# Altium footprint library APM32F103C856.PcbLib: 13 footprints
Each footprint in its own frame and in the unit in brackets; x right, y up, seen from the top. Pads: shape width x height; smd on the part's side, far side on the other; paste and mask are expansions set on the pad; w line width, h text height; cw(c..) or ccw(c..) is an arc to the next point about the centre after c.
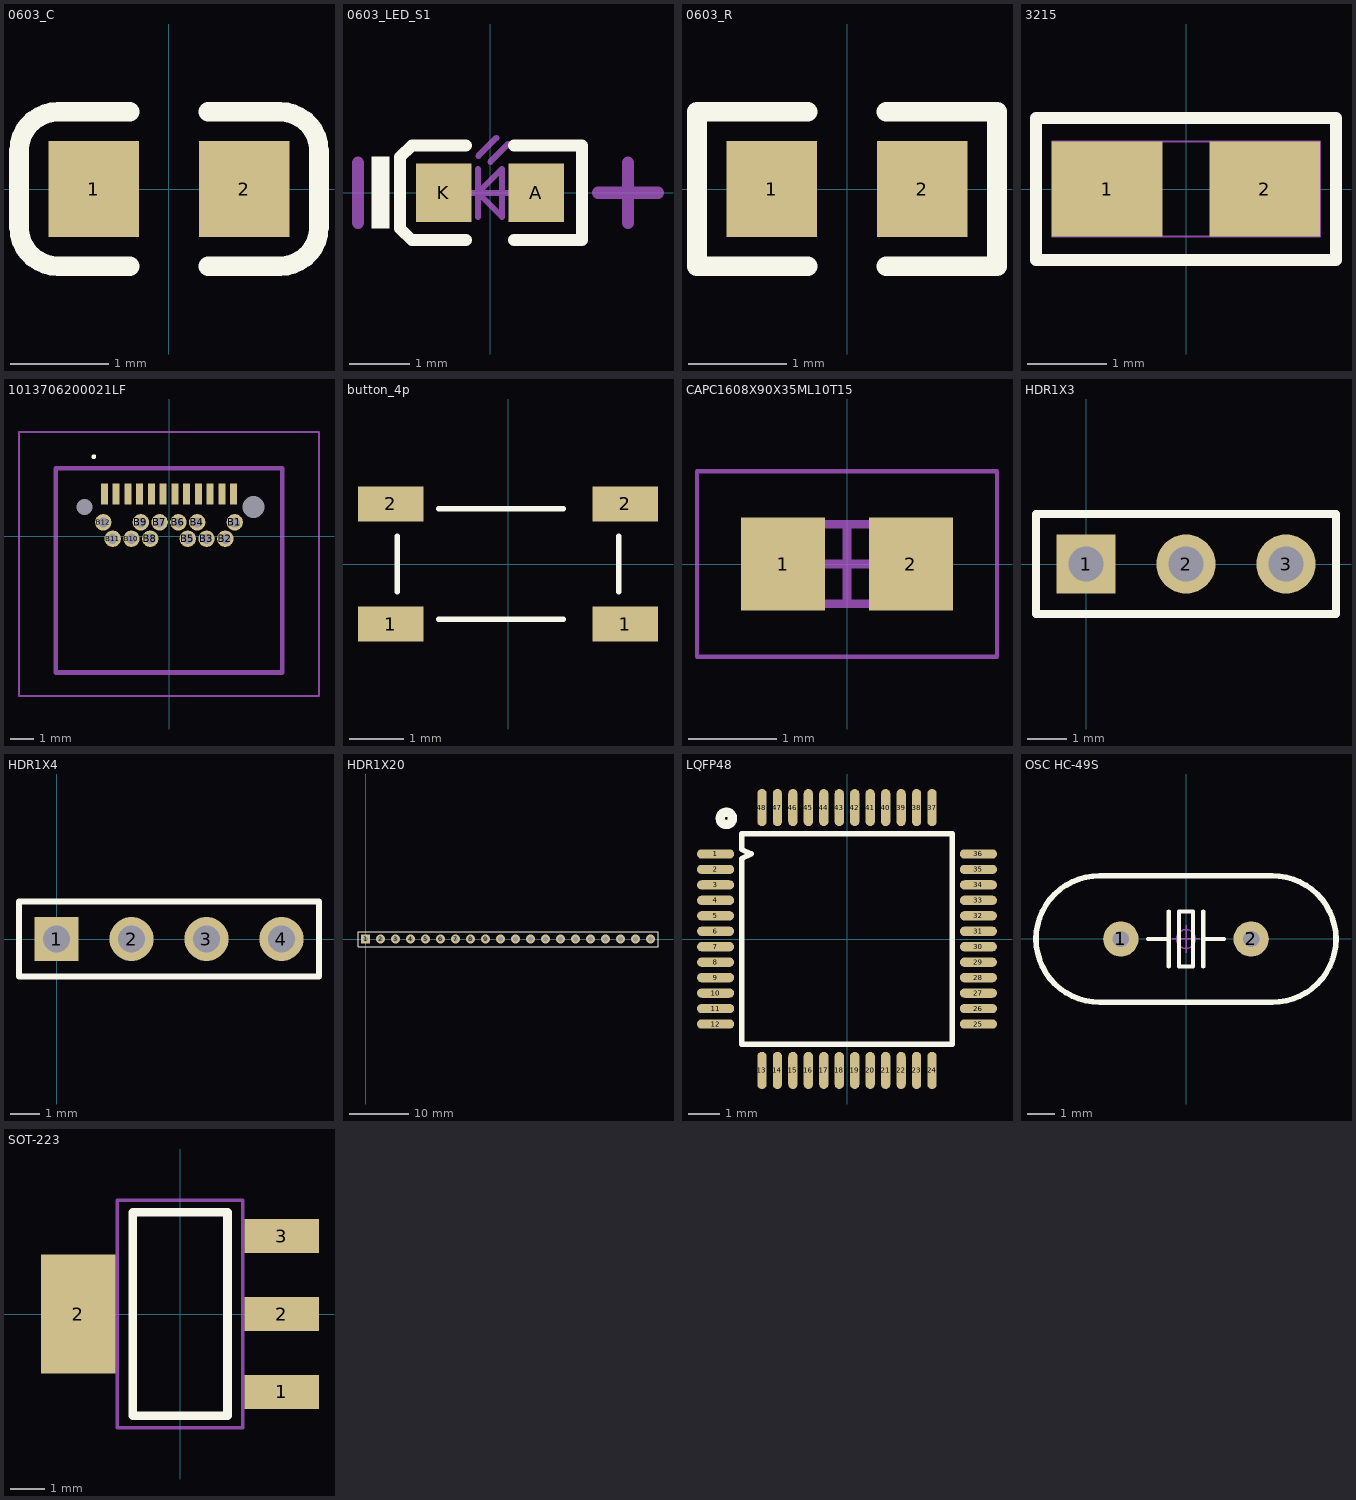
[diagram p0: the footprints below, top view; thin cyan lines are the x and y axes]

## 0603_C [mm]
pads (2):
  rect 0.93x0.98 smd paste+0: 1(-0.77,0)
  rect 0.93x0.98 smd: 2(0.77,0)
Top Overlay:
  lines w0.2: -0.4,-0.79 -1.135,-0.79 cw(c-1.135,-0.39) -1.535,-0.39 -1.535,0.39 cw(c-1.135,0.39) -1.135,0.79 -0.4,0.79 ; 0.4,-0.79 1.135,-0.79 ccw(c1.135,-0.39) 1.535,-0.39 1.535,0.39 ccw(c1.135,0.39) 1.135,0.79 0.4,0.79
3D body "User Library-0603 SMD Capacitor.STEP": height 0.3, standoff 0, extent -0.8,-0.4 0.8,0.4

## 0603_LED_S1 [mm]
pads (2):
  rect 0.93x0.98 smd: A(0.77,0) K(-0.77,0)
Top Overlay:
  rectangle: -1.975,-0.599 -1.675,0.601
  lines w0.2: -0.4,-0.79 -1.3,-0.79 -1.5,-0.597 -1.5,0.597 -1.3,0.79 -0.4,0.79 ; 0.4,-0.79 1.535,-0.79 1.535,0.79 0.4,0.79
Mechanical 13:
  lines w0.1: -0.4,0 0.4,0 ; -0.2,-0.4 -0.2,0.4 ; -0.195,0.617 0.105,0.917 ; 0.005,0.517 0.305,0.817 ; -0.2,0 0.2,-0.4 0.2,0.4 -0.2,0
Mechanical 15:
  lines w0.203: -2.2,-0.5 -2.2,0.5 ; 1.8,0 2.8,0 ; 2.3,-0.5 2.3,0.5
3D body "User Library-LED_0603_R.STEP": height 0.6, standoff 0, extent -0.8,-0.4 0.8,0.4

## 0603_R [mm]
pads (2):
  rect 0.93x0.98 smd: 1(-0.77,0) 2(0.77,0)
Top Overlay:
  lines w0.2: -0.4,-0.79 -1.535,-0.79 -1.535,0.79 -0.4,0.79 ; 0.4,-0.79 1.535,-0.79 1.535,0.79 0.4,0.79
3D body "User Library-RES_1609-0603.STEP": height 0.56, standoff 0, extent -0.85,-0.4 0.85,0.4

## 3215 [mm]
pads (2):
  rect 1.4x1.2 smd: 1(-1,0) 2(1,0)
Top Overlay:
  lines w0.15: -1.9,-0.9 -1.9,0.9 1.9,0.9 1.9,-0.9 -1.9,-0.9
Top Assembly:
  text "Y7" at -0.989,-0.635 h1.27
Mechanical 20:
  lines w0.025: -1.7,-0.6 1.7,-0.6 1.7,0.6 -1.7,0.6 -1.7,-0.6

## 1013706200021LF [mm]
pads (26):
  rect 0.3x0.9 smd: A1(-2.75,1.81) A2(-2.25,1.81) A3(-1.75,1.81) A4(-1.25,1.81) A5(-0.75,1.81) A6(-0.25,1.81) A7(0.25,1.81) A8(0.75,1.81) A9(1.25,1.81) A10(1.75,1.81) A11(2.25,1.81) A12(2.75,1.81)
  round 0.7 hole 0.43: B1(2.8,0.6) B2(2.4,-0.1) B3(1.6,-0.1) B4(1.2,0.6) B5(0.8,-0.1) B6(0.4,0.6) B7(-0.4,0.6) B8(-0.8,-0.1) B9(-1.2,0.6) B10(-1.6,-0.1) B11(-2.4,-0.1) B12(-2.8,0.6)
  round 0.338 hole 0.675 unplated: MH5(-3.6,1.25)
  round 0.475 hole 0.95 unplated: MH6(3.6,1.25)
Top Overlay:
  lines w0.1: -3.2,3.35 cw(c-3.2,3.4) -3.2,3.45 cw(c-3.2,3.4) -3.2,3.35
Mechanical 13:
  lines w0.2: -4.825,-5.8 -4.825,2.9 4.825,2.9 4.825,-5.8 -4.825,-5.8
Mechanical 15:
  lines w0.1: -6.39,-6.8 -6.39,4.45 6.39,4.45 6.39,-6.8 -6.39,-6.8
3D body "10137062-00021LF.stp": height 3.07, standoff -1.13, extent -4.825,-5.76 4.825,2.94

## button_4p [mm]
pads (4):
  rect 1.2x0.65 smd: 1(-2.15,-1.1) 1(2.15,-1.1) 2(-2.15,1.1) 2(2.15,1.1)
Top Overlay:
  lines w0.1: -2.032,-0.508 -2.032,0.508 ; -1.27,-1.016 1.016,-1.016 ; -1.27,1.016 1.016,1.016 ; 2.032,-0.508 2.032,0.508

## CAPC1608X90X35ML10T15 [mm] "Chip Capacitor, 2-Leads, Body 1.7x0.9mm, IPC Low Density"
height 0.9
pads (2):
  rect 0.95x1.05 smd: 1(-0.725,0) 2(0.725,0)
Mechanical 13:
  lines w0.1: -0.85,-0.45 -0.85,0.45 0.85,0.45 0.85,-0.45 -0.85,-0.45
Mechanical 15:
  lines w0.05: -1.7,-1.05 -1.7,1.05 1.7,1.05 1.7,-1.05 -1.7,-1.05
  lines w0.1: -0.45,0 0.45,0 ; 0,-0.45 0,0.45
3D body "CAPC1608X09M.step": height 0.9, standoff 0, extent -0.85,-0.45 0.85,0.45

## HDR1X3 [mm] "Connector; Header; 3 Position"
pads (3):
  rect 1.5x1.5 hole 0.9: 1(0,0)
  round 1.5 hole 0.9: 2(2.54,0) 3(5.08,0)
Top Overlay:
  lines w0.2: -1.27,-1.27 6.35,-1.27 6.35,1.27 -1.27,1.27 -1.27,-1.27

## HDR1X4 [mm] "Connector; Header; 4 Position"
pads (4):
  rect 1.5x1.5 hole 0.9: 1(0,0)
  round 1.5 hole 0.9: 2(2.54,0) 3(5.08,0) 4(7.62,0)
Top Overlay:
  lines w0.2: -1.27,-1.27 8.89,-1.27 8.89,1.27 -1.27,1.27 -1.27,-1.27

## HDR1X20 [mm] "Connector; Header; 20 Position"
pads (20):
  rect 1.5x1.5 hole 0.9: 1(0,0)
  round 1.5 hole 0.9: 2(2.54,0) 3(5.08,0) 4(7.62,0) 5(10.16,0) 6(12.7,0) 7(15.24,0) 8(17.78,0) 9(20.32,0) 10(22.86,0) 11(25.4,0) 12(27.94,0) 13(30.48,0) 14(33.02,0) 15(35.56,0) 16(38.1,0) 17(40.64,0) 18(43.18,0) 19(45.72,0) 20(48.26,0)
Top Overlay:
  lines w0.2: -1.27,-1.27 -1.27,1.27 0.635,1.27 49.53,1.27 49.53,-1.27 -1.27,-1.27

## LQFP48 [mm]
pads (48):
  oval 1.2x0.3 smd: 1(-4.25,2.75) 2(-4.25,2.25) 3(-4.25,1.75) 4(-4.25,1.25) 5(-4.25,0.75) 6(-4.25,0.25) 7(-4.25,-0.25) 8(-4.25,-0.75) 9(-4.25,-1.25) 10(-4.25,-1.75) 11(-4.25,-2.25) 12(-4.25,-2.75) 25(4.25,-2.75) 26(4.25,-2.25) 27(4.25,-1.75) 28(4.25,-1.25) 29(4.25,-0.75) 30(4.25,-0.25) 31(4.25,0.25) 32(4.25,0.75) 33(4.25,1.25) 34(4.25,1.75) 35(4.25,2.25) 36(4.25,2.75)
  oval 0.3x1.2 smd: 13(-2.75,-4.25) 14(-2.25,-4.25) 15(-1.75,-4.25) 16(-1.25,-4.25) 17(-0.75,-4.25) 18(-0.25,-4.25) 19(0.25,-4.25) 20(0.75,-4.25) 21(1.25,-4.25) 22(1.75,-4.25) 23(2.25,-4.25) 24(2.75,-4.25) 37(2.75,4.25) 38(2.25,4.25) 39(1.75,4.25) 40(1.25,4.25) 41(0.75,4.25) 42(0.25,4.25) 43(-0.25,4.25) 44(-0.75,4.25) 45(-1.25,4.25) 46(-1.75,4.25) 47(-2.25,4.25) 48(-2.75,4.25)
Top Overlay:
  lines w0.178: -3.4,-3.4 3.4,-3.4 3.4,3.4 -3.4,3.4 -3.4,2.9 -3.1,2.75 -3.4,2.6 -3.4,-3.4
  lines w0.3: -3.759,4.041 ccw(c-3.9,3.9) -3.756,4.038

## OSC HC-49S [mm]
pads (2):
  round 1.3 hole 0.6: 1(-2.4,0) 2(2.4,0)
Top Overlay:
  lines w0.152: -1.397,0 -0.635,0 ; -0.635,-1.016 -0.635,1.016 ; 0.635,-1.016 0.635,1.016 ; 0.635,0 1.397,0 ; -0.254,-1.016 0.254,-1.016 0.254,1.016 -0.254,1.016 -0.254,-1.016
  lines w0.203: -3.175,2.325 ccw(c-3.2,0) -3.173,-2.325 3.175,-2.325 ccw(c3.2,0) 3.173,2.325 -3.175,2.325
Mechanical 15:
  circle w0.05: c0,0 r0.35
  lines w0.05: -0.5,0 0.5,0 ; 0,-0.5 0,0.5
3D body "OSC HC-49S.STEP": height 4.13, standoff -3.45, extent -5.525,-2.325 5.525,2.325

## SOT-223 [mm]
pads (4):
  rect 2.2x1 smd: 1(3,-2.3) 2(3,0) 3(3,2.3)
  rect 2.2x3.5 smd: 2(-3,0)
Top Overlay:
  lines w0.254: -1.4,-3 1.4,-3 1.4,3 -1.4,3 -1.4,-3
Mechanical 13:
  lines w0.1: -1.85,-3.35 -1.85,3.35 1.85,3.35 1.85,-3.35 -1.85,-3.35
3D body "TO-223.STEP": height 1.64, standoff -0.04, extent -3.49,-3.242 3.49,3.243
